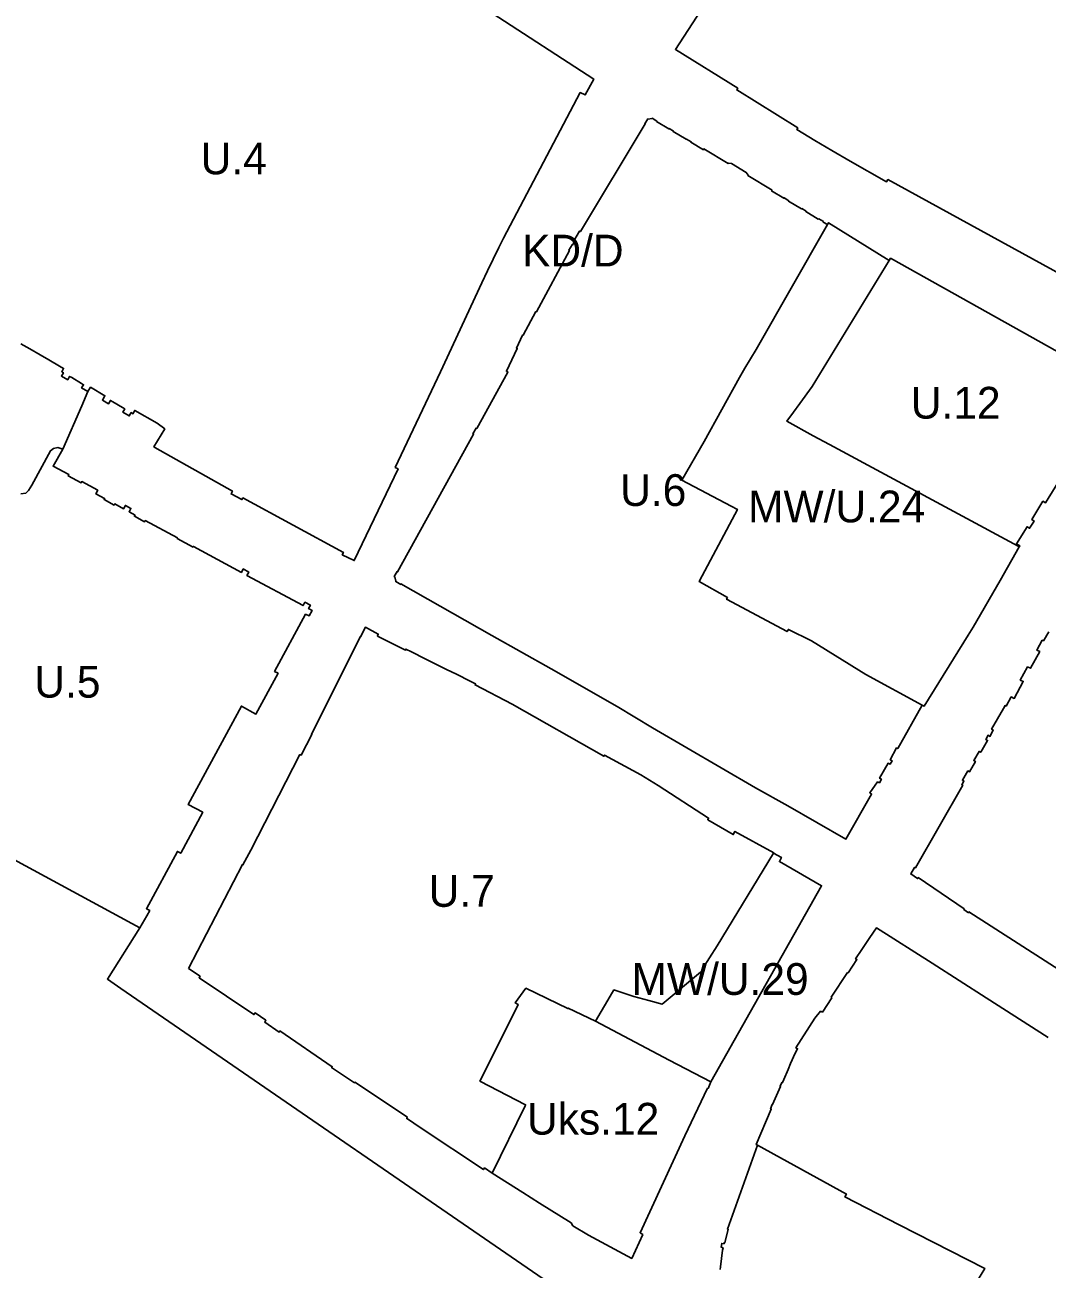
# Model space of a CAD drawing. Extents: x 7423367 to 7424726, y 5546744 to 5548391.
# Drawn here: x 7423601.6 to 7423762.4, y 5547645 to 5547840.8 of the extents above; entities that cross this region are included whole.
import ezdxf

# ---------------------------------------------------------------- set-up
doc = ezdxf.new("R2010")
doc.units = 0
doc.layers.add('linie_rozgraniczajace', color=7, linetype='Continuous')
doc.layers.add('oznaczenia_przeznaczen', color=7, linetype='Continuous')

msp = doc.modelspace()

# ---------------------------------------------------------------- linework, layer by layer
at = {"layer": 'linie_rozgraniczajace'}
for points in [[(7423766.63, 5547800.41), (7423737.4, 5547816.48), (7423737.16, 5547816.11), (7423731.47, 5547819.36), (7423728.55, 5547821.04), (7423725.88, 5547822.62), (7423723.06, 5547824.37), (7423723.22, 5547824.61), (7423713.61, 5547830.6), (7423713.76, 5547830.85), (7423703.96, 5547836.97), (7423711.24, 5547848.23)], [(7423711.24, 5547848.23), (7423703.96, 5547836.97), (7423713.76, 5547830.85), (7423713.61, 5547830.6), (7423723.22, 5547824.61), (7423723.06, 5547824.37), (7423725.88, 5547822.62), (7423728.55, 5547821.04), (7423731.47, 5547819.36), (7423737.16, 5547816.11), (7423737.4, 5547816.48), (7423766.63, 5547800.41)], [(7423675.14, 5547842.66), (7423691.1, 5547832.28), (7423689.77, 5547829.8), (7423688.99, 5547830.18), (7423676.92, 5547807.25), (7423676.17, 5547805.8), (7423674.4, 5547802.11), (7423673.49, 5547800.21), (7423667.01, 5547786.22), (7423659.87, 5547771.16), (7423660.33, 5547770.92), (7423653.43, 5547756.48), (7423651.54, 5547757.4), (7423651.72, 5547757.77), (7423635.91, 5547766.37), (7423635.74, 5547766.1), (7423634.04, 5547766.98), (7423634.25, 5547767.44), (7423622.05, 5547774.29), (7423621.9, 5547774.38), (7423623.61, 5547777.23), (7423622.44, 5547778.13), (7423618.9, 5547780.14), (7423618.6, 5547779.62), (7423618.33, 5547779.78), (7423618.03, 5547779.26), (7423617.02, 5547779.85), (7423617.32, 5547780.37), (7423616.98, 5547780.57), (7423615.42, 5547781.49), (7423615.07, 5547781.7), (7423614.77, 5547781.18), (7423613.79, 5547781.76), (7423614.19, 5547782.45), (7423611.93, 5547783.78), (7423611.52, 5547783.09), (7423610.52, 5547783.68), (7423610.85, 5547784.18), (7423610.5, 5547784.39), (7423608.97, 5547785.29), (7423608.63, 5547785.49), (7423608.34, 5547784.96), (7423607.35, 5547785.55), (7423607.66, 5547786.06), (7423607.4, 5547786.22), (7423607.68, 5547786.74), (7423607.04, 5547787.12), (7423605.39, 5547788.08), (7423604, 5547788.87), (7423602.36, 5547789.82), (7423600.97, 5547790.62)], [(7423690.72, 5547638.24), (7423616.68, 5547689.14), (7423614.59, 5547690.6), (7423619.69, 5547698.66), (7423620.8, 5547700.55), (7423621.24, 5547701.39), (7423620.72, 5547701.68), (7423625.6, 5547710.71), (7423626.13, 5547710.43), (7423629.58, 5547716.88), (7423627.28, 5547718.1), (7423635.66, 5547733.59), (7423637.96, 5547732.34), (7423641.44, 5547738.76), (7423640.9, 5547739.04), (7423645.76, 5547748.04), (7423646.31, 5547747.77), (7423646.78, 5547748.65), (7423646.25, 5547748.93), (7423646.53, 5547749.46), (7423645.66, 5547749.94), (7423645.37, 5547749.41), (7423636.55, 5547754.17), (7423636.83, 5547754.69), (7423635.96, 5547755.17), (7423635.67, 5547754.64), (7423628.12, 5547758.72), (7423628.07, 5547758.63), (7423625.56, 5547759.97), (7423625.6, 5547760.06), (7423620.53, 5547762.78), (7423620.44, 5547762.6), (7423618.84, 5547763.46), (7423618.93, 5547763.62), (7423618, 5547764.19), (7423618.29, 5547764.71), (7423617.42, 5547765.19), (7423617.13, 5547764.66), (7423615.74, 5547765.41), (7423615.65, 5547765.24), (7423614.06, 5547766.1), (7423614.15, 5547766.27), (7423612.77, 5547767), (7423613.07, 5547767.57), (7423610.55, 5547768.93), (7423610.44, 5547768.73), (7423608.43, 5547769.81), (7423608.54, 5547770.02), (7423606.03, 5547771.35), (7423607.56, 5547774.04), (7423610.55, 5547780.86), (7423611.52, 5547783.09), (7423611.93, 5547783.78), (7423614.19, 5547782.45), (7423613.79, 5547781.76), (7423614.77, 5547781.18), (7423615.07, 5547781.7), (7423615.42, 5547781.49), (7423616.98, 5547780.57), (7423617.32, 5547780.37), (7423617.02, 5547779.85), (7423618.03, 5547779.26), (7423618.33, 5547779.78), (7423618.6, 5547779.62), (7423618.9, 5547780.14), (7423622.44, 5547778.13), (7423623.61, 5547777.23), (7423621.9, 5547774.38), (7423622.05, 5547774.29), (7423634.25, 5547767.44), (7423634.04, 5547766.98), (7423635.74, 5547766.1), (7423635.91, 5547766.37), (7423651.72, 5547757.77), (7423651.54, 5547757.4), (7423653.43, 5547756.48), (7423660.33, 5547770.92), (7423659.87, 5547771.16), (7423667.01, 5547786.22), (7423673.49, 5547800.21), (7423674.4, 5547802.11), (7423676.17, 5547805.8), (7423676.92, 5547807.25), (7423688.99, 5547830.18), (7423689.77, 5547829.8), (7423691.1, 5547832.28), (7423675.14, 5547842.66)], [(7423764.13, 5547789.34), (7423737.82, 5547804.09), (7423737.6, 5547803.72), (7423728.07, 5547809.68), (7423727.89, 5547809.38), (7423727.2, 5547809.79), (7423727.24, 5547809.85), (7423726.5, 5547810.29), (7423726.43, 5547810.26), (7423724.49, 5547811.43), (7423724.52, 5547811.48), (7423723.86, 5547811.9), (7423723.78, 5547811.85), (7423721.77, 5547813.05), (7423721.81, 5547813.12), (7423721.07, 5547813.61), (7423721.03, 5547813.53), (7423719.1, 5547814.7), (7423719.16, 5547814.8), (7423715.36, 5547817.09), (7423715.39, 5547817.18), (7423715.11, 5547817.59), (7423712.76, 5547818.99), (7423712.3, 5547819.06), (7423712.24, 5547819), (7423708.43, 5547821.29), (7423708.36, 5547821.17), (7423706.39, 5547822.36), (7423706.43, 5547822.42), (7423705.68, 5547822.86), (7423705.64, 5547822.81), (7423703.62, 5547824.04), (7423703.65, 5547824.1), (7423703, 5547824.49), (7423702.94, 5547824.46), (7423700.98, 5547825.63), (7423701.01, 5547825.67), (7423700.29, 5547826.12), (7423700.23, 5547826.08), (7423699.65, 5547825.99), (7423699.61, 5547826.01), (7423699.13, 5547825.27), (7423699.18, 5547825.23), (7423689.02, 5547808.28), (7423688.87, 5547808.37), (7423687.97, 5547806.84), (7423688.09, 5547806.77), (7423687.76, 5547806.16), (7423687.7, 5547806.2), (7423687.18, 5547805.36), (7423687.27, 5547805.3), (7423682.12, 5547795.64), (7423682, 5547795.7), (7423680.03, 5547791.98), (7423679.92, 5547791.99), (7423678.94, 5547789.95), (7423679.08, 5547789.89), (7423677.37, 5547786.29), (7423677.61, 5547786.17), (7423672.7, 5547777.3), (7423672.6, 5547777.34), (7423672.11, 5547776.45), (7423672.19, 5547776.41), (7423660.24, 5547754.71), (7423660.16, 5547754.75), (7423659.73, 5547753.98), (7423659.79, 5547753.95), (7423659.97, 5547753.24), (7423659.95, 5547753.19), (7423660.73, 5547752.75), (7423660.77, 5547752.82), (7423675.09, 5547744.71), (7423684.39, 5547739.43), (7423694.82, 5547733.51), (7423700.34, 5547730.18), (7423716.57, 5547720.74), (7423721.66, 5547717.88), (7423730.78, 5547712.64), (7423734.83, 5547719.73), (7423734.54, 5547719.94), (7423735.76, 5547721.66), (7423736.05, 5547721.51), (7423736.36, 5547722.07), (7423736.08, 5547722.22), (7423737.43, 5547724.6), (7423737.73, 5547724.43), (7423738.04, 5547724.99), (7423737.75, 5547725.15), (7423738.77, 5547726.99), (7423738.93, 5547726.9), (7423742.81, 5547733.71), (7423743.08, 5547733.55), (7423750.01, 5547744.74), (7423750.79, 5547746), (7423755.07, 5547753.38), (7423758.07, 5547758.65), (7423758.16, 5547758.81), (7423757.62, 5547759.14), (7423759.29, 5547761.83), (7423759.68, 5547761.58), (7423760.4, 5547762.7), (7423760.03, 5547762.97), (7423761.79, 5547765.84), (7423762.21, 5547765.59), (7423765.23, 5547770.52)], [(7423765.23, 5547770.52), (7423762.21, 5547765.59), (7423761.79, 5547765.84), (7423760.03, 5547762.97), (7423760.4, 5547762.7), (7423759.68, 5547761.58), (7423759.29, 5547761.83), (7423757.62, 5547759.14), (7423758.16, 5547758.81), (7423758.07, 5547758.65), (7423757.9, 5547758.76), (7423728.19, 5547774.78), (7423725.65, 5547776.14), (7423721.48, 5547778.45), (7423722.53, 5547779.86), (7423723.56, 5547781.22), (7423725.48, 5547783.89), (7423737.6, 5547803.72), (7423737.82, 5547804.09), (7423764.13, 5547789.34)], [(7423600.97, 5547790.62), (7423602.36, 5547789.82), (7423604, 5547788.87), (7423605.39, 5547788.08), (7423607.04, 5547787.12), (7423607.68, 5547786.74), (7423607.4, 5547786.22), (7423607.66, 5547786.06), (7423607.35, 5547785.55), (7423608.34, 5547784.96), (7423608.63, 5547785.49), (7423608.97, 5547785.29), (7423610.5, 5547784.39), (7423610.85, 5547784.18), (7423610.52, 5547783.68), (7423611.52, 5547783.09), (7423610.55, 5547780.86), (7423607.56, 5547774.04), (7423606.79, 5547774.28), (7423606.12, 5547774.15), (7423605.62, 5547773.78), (7423602.7, 5547768.37), (7423602.15, 5547767.5), (7423601.74, 5547767.1), (7423600.97, 5547766.99)], [(7423600.97, 5547766.99), (7423601.74, 5547767.1), (7423602.15, 5547767.5), (7423602.7, 5547768.37), (7423605.62, 5547773.78), (7423606.12, 5547774.15), (7423606.79, 5547774.28), (7423607.56, 5547774.04), (7423606.03, 5547771.35), (7423608.54, 5547770.02), (7423608.43, 5547769.81), (7423610.44, 5547768.73), (7423610.55, 5547768.93), (7423613.07, 5547767.57), (7423612.77, 5547767), (7423614.15, 5547766.27), (7423614.06, 5547766.1), (7423615.65, 5547765.24), (7423615.74, 5547765.41), (7423617.13, 5547764.66), (7423617.42, 5547765.19), (7423618.29, 5547764.71), (7423618, 5547764.19), (7423618.93, 5547763.62), (7423618.84, 5547763.46), (7423620.44, 5547762.6), (7423620.53, 5547762.78), (7423625.6, 5547760.06), (7423625.56, 5547759.97), (7423628.07, 5547758.63), (7423628.12, 5547758.72), (7423635.67, 5547754.64), (7423635.96, 5547755.17), (7423636.83, 5547754.69), (7423636.55, 5547754.17), (7423645.37, 5547749.41), (7423645.66, 5547749.94), (7423646.53, 5547749.46), (7423646.25, 5547748.93), (7423646.78, 5547748.65), (7423646.31, 5547747.77), (7423645.76, 5547748.04), (7423640.9, 5547739.04), (7423641.44, 5547738.76), (7423637.96, 5547732.34), (7423635.66, 5547733.59), (7423627.28, 5547718.1), (7423629.58, 5547716.88), (7423626.13, 5547710.43), (7423625.6, 5547710.71), (7423620.72, 5547701.68), (7423621.24, 5547701.39), (7423620.8, 5547700.55), (7423619.69, 5547698.66), (7423578.71, 5547720.88)], [(7423770.65, 5547688.01), (7423750.15, 5547701.19), (7423750.06, 5547701.06), (7423749.32, 5547701.58), (7423749.37, 5547701.69), (7423742.18, 5547706.59), (7423742.07, 5547706.44), (7423740.98, 5547707.17), (7423741.59, 5547708.19), (7423741.72, 5547708.12), (7423749.16, 5547721.12), (7423749.02, 5547721.2), (7423749.36, 5547721.79), (7423749.13, 5547721.92), (7423749.97, 5547723.38), (7423750.23, 5547723.22), (7423751.16, 5547724.87), (7423750.91, 5547725.02), (7423751.73, 5547726.46), (7423751.99, 5547726.31), (7423753.08, 5547728.18), (7423752.79, 5547728.35), (7423753.16, 5547728.99), (7423753.45, 5547728.81), (7423753.98, 5547729.8), (7423753.71, 5547729.96), (7423755.59, 5547733.23), (7423755.85, 5547733.68), (7423755.99, 5547733.59), (7423756.8, 5547735.03), (7423757.27, 5547734.79), (7423758.68, 5547737.46), (7423758.21, 5547737.69), (7423759.37, 5547739.76), (7423759.84, 5547739.55), (7423761.29, 5547742.16), (7423760.83, 5547742.39), (7423761.69, 5547743.94), (7423761.85, 5547743.87), (7423762.72, 5547745.26)], [(7423762.72, 5547745.26), (7423761.85, 5547743.87), (7423761.69, 5547743.94), (7423760.83, 5547742.39), (7423761.29, 5547742.16), (7423759.84, 5547739.55), (7423759.37, 5547739.76), (7423758.21, 5547737.69), (7423758.68, 5547737.46), (7423757.27, 5547734.79), (7423756.8, 5547735.03), (7423755.99, 5547733.59), (7423755.85, 5547733.68), (7423755.59, 5547733.23), (7423753.71, 5547729.96), (7423753.98, 5547729.8), (7423753.45, 5547728.81), (7423753.16, 5547728.99), (7423752.79, 5547728.35), (7423753.08, 5547728.18), (7423751.99, 5547726.31), (7423751.73, 5547726.46), (7423750.91, 5547725.02), (7423751.16, 5547724.87), (7423750.23, 5547723.22), (7423749.97, 5547723.38), (7423749.13, 5547721.92), (7423749.36, 5547721.79), (7423749.02, 5547721.2), (7423749.16, 5547721.12), (7423741.72, 5547708.12), (7423741.59, 5547708.19), (7423740.98, 5547707.17), (7423742.07, 5547706.44), (7423742.18, 5547706.59), (7423749.37, 5547701.69), (7423749.32, 5547701.58), (7423750.06, 5547701.06), (7423750.15, 5547701.19), (7423770.65, 5547688.01)], [(7423578.71, 5547720.88), (7423619.69, 5547698.66), (7423614.59, 5547690.6), (7423616.68, 5547689.14), (7423690.72, 5547638.24)], [(7423762.6, 5547681.43), (7423752.86, 5547687.68), (7423744.35, 5547693.13), (7423735.6, 5547698.7), (7423734.56, 5547697.15), (7423733.3, 5547695.29), (7423732.3, 5547693.78), (7423732.52, 5547693.67), (7423731.15, 5547691.6), (7423731.04, 5547691.63), (7423728.49, 5547687.75), (7423728.55, 5547687.66), (7423727.08, 5547685.42), (7423726.81, 5547685.56), (7423725.87, 5547684.47), (7423722.92, 5547679.78), (7423723.17, 5547679.65), (7423722.79, 5547678.94), (7423722.08, 5547677.34), (7423721.68, 5547676.38), (7423721, 5547674.8), (7423720.81, 5547674.33), (7423720.71, 5547674.35), (7423720.43, 5547673.74), (7423720.5, 5547673.68), (7423719.25, 5547670.87), (7423719.16, 5547670.86), (7423718.93, 5547670.16), (7423719.05, 5547670.14), (7423716.69, 5547664.56), (7423716.88, 5547664.46), (7423712.13, 5547651.26), (7423712.28, 5547651.22), (7423711.76, 5547649.1), (7423711.62, 5547649.14), (7423711.61, 5547648.95), (7423711.25, 5547648.99), (7423711.16, 5547648.39), (7423711.46, 5547648.32), (7423711.39, 5547647.91), (7423711.07, 5547645.3), (7423711.02, 5547644.88)], [(7423749.78, 5547640.35), (7423752.65, 5547645.04), (7423739.17, 5547651.95), (7423730.63, 5547656.33), (7423730.86, 5547656.77), (7423716.88, 5547664.46), (7423716.69, 5547664.56), (7423719.05, 5547670.14), (7423718.93, 5547670.16), (7423719.16, 5547670.86), (7423719.25, 5547670.87), (7423720.5, 5547673.68), (7423720.43, 5547673.74), (7423720.71, 5547674.35), (7423720.81, 5547674.33), (7423721, 5547674.8), (7423721.68, 5547676.38), (7423722.08, 5547677.34), (7423722.79, 5547678.94), (7423723.17, 5547679.65), (7423722.92, 5547679.78), (7423725.87, 5547684.47), (7423726.81, 5547685.56), (7423727.08, 5547685.42), (7423728.55, 5547687.66), (7423728.49, 5547687.75), (7423731.04, 5547691.63), (7423731.15, 5547691.6), (7423732.52, 5547693.67), (7423732.3, 5547693.78), (7423733.3, 5547695.29), (7423734.56, 5547697.15), (7423735.6, 5547698.7), (7423744.35, 5547693.13), (7423752.86, 5547687.68), (7423762.6, 5547681.43)], [(7423711.02, 5547644.88), (7423711.07, 5547645.3), (7423711.39, 5547647.91), (7423711.46, 5547648.32), (7423711.16, 5547648.39), (7423711.25, 5547648.99), (7423711.61, 5547648.95), (7423711.62, 5547649.14), (7423711.76, 5547649.1), (7423712.28, 5547651.22), (7423712.13, 5547651.26), (7423716.88, 5547664.46), (7423730.86, 5547656.77), (7423730.63, 5547656.33), (7423739.17, 5547651.95), (7423752.65, 5547645.04), (7423749.78, 5547640.35)]]:
    msp.add_lwpolyline(points, dxfattribs=at)
for points in [[(7423659.73, 5547753.98), (7423660.16, 5547754.75), (7423660.24, 5547754.71), (7423672.19, 5547776.41), (7423672.11, 5547776.45), (7423672.6, 5547777.34), (7423672.7, 5547777.3), (7423677.61, 5547786.17), (7423677.37, 5547786.29), (7423679.08, 5547789.89), (7423678.94, 5547789.95), (7423679.92, 5547791.99), (7423680.03, 5547791.98), (7423682, 5547795.7), (7423682.12, 5547795.64), (7423687.27, 5547805.3), (7423687.18, 5547805.36), (7423687.7, 5547806.2), (7423687.76, 5547806.16), (7423688.09, 5547806.77), (7423687.97, 5547806.84), (7423688.87, 5547808.37), (7423689.02, 5547808.28), (7423699.18, 5547825.23), (7423699.13, 5547825.27), (7423699.61, 5547826.01), (7423699.65, 5547825.99), (7423700.23, 5547826.08), (7423700.29, 5547826.12), (7423701.01, 5547825.67), (7423700.98, 5547825.63), (7423702.94, 5547824.46), (7423703, 5547824.49), (7423703.65, 5547824.1), (7423703.62, 5547824.04), (7423705.64, 5547822.81), (7423705.68, 5547822.86), (7423706.43, 5547822.42), (7423706.39, 5547822.36), (7423708.36, 5547821.17), (7423708.43, 5547821.29), (7423712.24, 5547819), (7423712.3, 5547819.06), (7423712.76, 5547818.99), (7423715.11, 5547817.59), (7423715.39, 5547817.18), (7423715.36, 5547817.09), (7423719.16, 5547814.8), (7423719.1, 5547814.7), (7423721.03, 5547813.53), (7423721.07, 5547813.61), (7423721.81, 5547813.12), (7423721.77, 5547813.05), (7423723.78, 5547811.85), (7423723.86, 5547811.9), (7423724.52, 5547811.48), (7423724.49, 5547811.43), (7423726.43, 5547810.26), (7423726.5, 5547810.29), (7423727.24, 5547809.85), (7423727.2, 5547809.79), (7423727.89, 5547809.38), (7423716.65, 5547789.74), (7423714.87, 5547786.8), (7423714.03, 5547785.32), (7423708.47, 5547775.24), (7423704.98, 5547769.14), (7423712.73, 5547765.08), (7423713.72, 5547764.56), (7423707.75, 5547753.3), (7423707.7, 5547753.2), (7423712.15, 5547750.67), (7423712.01, 5547750.4), (7423721.52, 5547745.31), (7423721.75, 5547745.65), (7423725.35, 5547743.84), (7423733.94, 5547738.57), (7423742.81, 5547733.71), (7423738.93, 5547726.9), (7423738.77, 5547726.99), (7423737.75, 5547725.15), (7423738.04, 5547724.99), (7423737.73, 5547724.43), (7423737.43, 5547724.6), (7423736.08, 5547722.22), (7423736.36, 5547722.07), (7423736.05, 5547721.51), (7423735.76, 5547721.66), (7423734.54, 5547719.94), (7423734.83, 5547719.73), (7423730.78, 5547712.64), (7423721.66, 5547717.88), (7423716.57, 5547720.74), (7423700.34, 5547730.18), (7423694.82, 5547733.51), (7423684.39, 5547739.43), (7423675.09, 5547744.71), (7423660.77, 5547752.82), (7423660.73, 5547752.75), (7423659.95, 5547753.19), (7423659.97, 5547753.24), (7423659.79, 5547753.95)], [(7423704.98, 5547769.14), (7423708.47, 5547775.24), (7423714.03, 5547785.32), (7423714.87, 5547786.8), (7423716.65, 5547789.74), (7423727.89, 5547809.38), (7423728.07, 5547809.68), (7423737.6, 5547803.72), (7423725.48, 5547783.89), (7423723.56, 5547781.22), (7423722.53, 5547779.86), (7423721.48, 5547778.45), (7423725.65, 5547776.14), (7423728.19, 5547774.78), (7423757.9, 5547758.76), (7423758.07, 5547758.65), (7423755.07, 5547753.38), (7423750.79, 5547746), (7423750.01, 5547744.74), (7423743.08, 5547733.55), (7423742.81, 5547733.71), (7423733.94, 5547738.57), (7423725.35, 5547743.84), (7423721.75, 5547745.65), (7423721.52, 5547745.31), (7423712.01, 5547750.4), (7423712.15, 5547750.67), (7423707.7, 5547753.2), (7423707.75, 5547753.3), (7423713.72, 5547764.56), (7423712.73, 5547765.08)], [(7423627.36, 5547692.29), (7423635.82, 5547708.63), (7423635.92, 5547708.58), (7423637.13, 5547710.93), (7423644.87, 5547725.95), (7423645.06, 5547725.86), (7423646.76, 5547729.09), (7423646.69, 5547729.13), (7423654.35, 5547744.5), (7423654.42, 5547744.48), (7423655.19, 5547746), (7423657.21, 5547744.93), (7423657.06, 5547744.62), (7423661.47, 5547742.38), (7423661.55, 5547742.55), (7423662.41, 5547742.12), (7423664.6, 5547741.03), (7423665.76, 5547740.46), (7423667.96, 5547739.36), (7423669.49, 5547738.62), (7423671.69, 5547737.5), (7423672.53, 5547737.09), (7423672.45, 5547736.92), (7423678.26, 5547733.87), (7423692.72, 5547725.7), (7423692.82, 5547725.87), (7423698.54, 5547722.74), (7423701.25, 5547721.08), (7423709.19, 5547715.95), (7423709.05, 5547715.69), (7423713.07, 5547713.37), (7423713.33, 5547713.87), (7423719.44, 5547710.49), (7423719.41, 5547710.41), (7423710.54, 5547695.82), (7423708.14, 5547692.09), (7423708.22, 5547692.02), (7423707.92, 5547691.69), (7423701.87, 5547686.67), (7423699.78, 5547687.24), (7423697.41, 5547687.89), (7423694.28, 5547688.91), (7423693.67, 5547687.94), (7423691.41, 5547683.97), (7423687.1, 5547686.05), (7423687.05, 5547685.96), (7423680.43, 5547689.17), (7423678.77, 5547686.85), (7423679.21, 5547686.62), (7423678.88, 5547685.92), (7423673.21, 5547674.56), (7423680.39, 5547670.82), (7423680.31, 5547670.67), (7423675.15, 5547660.07), (7423673.93, 5547660.88), (7423673.76, 5547660.62), (7423663.96, 5547667.16), (7423661.67, 5547668.7), (7423661.78, 5547668.86), (7423653.53, 5547674.39), (7423653.44, 5547674.26), (7423649.87, 5547676.68), (7423649.96, 5547676.81), (7423641.74, 5547682.44), (7423641.62, 5547682.26), (7423639.34, 5547683.82), (7423639.53, 5547684.13), (7423637.82, 5547685.29), (7423637.64, 5547685.02), (7423629.01, 5547690.81), (7423629.18, 5547691.07)], [(7423627.36, 5547692.29), (7423629.18, 5547691.07), (7423629.01, 5547690.81), (7423637.64, 5547685.02), (7423637.82, 5547685.29), (7423639.53, 5547684.13), (7423639.34, 5547683.82), (7423641.62, 5547682.26), (7423641.74, 5547682.44), (7423649.96, 5547676.81), (7423649.87, 5547676.68), (7423653.44, 5547674.26), (7423653.53, 5547674.39), (7423661.78, 5547668.86), (7423661.67, 5547668.7), (7423663.96, 5547667.16), (7423673.76, 5547660.62), (7423673.93, 5547660.88), (7423675.15, 5547660.07), (7423679.95, 5547657.03), (7423682.55, 5547655.31), (7423687.55, 5547652.24), (7423687.8, 5547651.79), (7423690.26, 5547650.32), (7423697.08, 5547646.65), (7423698.83, 5547650.38), (7423698.39, 5547650.69), (7423705.44, 5547665.93), (7423709.01, 5547673.42), (7423709.11, 5547673.41), (7423709.54, 5547674.41), (7423726.96, 5547705.31), (7423720.33, 5547709.12), (7423720.64, 5547709.76), (7423719.41, 5547710.41), (7423719.44, 5547710.49), (7423713.33, 5547713.87), (7423713.07, 5547713.37), (7423709.05, 5547715.69), (7423709.19, 5547715.95), (7423701.25, 5547721.08), (7423698.54, 5547722.74), (7423692.82, 5547725.87), (7423692.72, 5547725.7), (7423678.26, 5547733.87), (7423672.45, 5547736.92), (7423672.53, 5547737.09), (7423671.69, 5547737.5), (7423669.49, 5547738.62), (7423667.96, 5547739.36), (7423665.76, 5547740.46), (7423664.6, 5547741.03), (7423662.41, 5547742.12), (7423661.55, 5547742.55), (7423661.47, 5547742.38), (7423657.06, 5547744.62), (7423657.21, 5547744.93), (7423655.19, 5547746), (7423654.42, 5547744.48), (7423654.35, 5547744.5), (7423646.69, 5547729.13), (7423646.76, 5547729.09), (7423645.06, 5547725.86), (7423644.87, 5547725.95), (7423637.13, 5547710.93), (7423635.92, 5547708.58), (7423635.82, 5547708.63)], [(7423691.41, 5547683.97), (7423693.67, 5547687.94), (7423694.28, 5547688.91), (7423697.41, 5547687.89), (7423699.78, 5547687.24), (7423701.87, 5547686.67), (7423707.92, 5547691.69), (7423708.22, 5547692.02), (7423708.14, 5547692.09), (7423710.54, 5547695.82), (7423719.41, 5547710.41), (7423720.64, 5547709.76), (7423720.33, 5547709.12), (7423726.96, 5547705.31), (7423709.54, 5547674.41), (7423702.98, 5547677.87)], [(7423673.21, 5547674.56), (7423678.88, 5547685.92), (7423679.21, 5547686.62), (7423678.77, 5547686.85), (7423680.43, 5547689.17), (7423687.05, 5547685.96), (7423687.1, 5547686.05), (7423691.41, 5547683.97), (7423702.98, 5547677.87), (7423709.54, 5547674.41), (7423709.11, 5547673.41), (7423709.01, 5547673.42), (7423705.44, 5547665.93), (7423698.39, 5547650.69), (7423698.83, 5547650.38), (7423697.08, 5547646.65), (7423690.26, 5547650.32), (7423687.8, 5547651.79), (7423687.55, 5547652.24), (7423682.55, 5547655.31), (7423679.95, 5547657.03), (7423675.15, 5547660.07), (7423680.31, 5547670.67), (7423680.39, 5547670.82)]]:
    msp.add_lwpolyline(points, close=True, dxfattribs=at)

# ---------------------------------------------------------------- texts
at = {"layer": 'oznaczenia_przeznaczen'}
for s, p in [('U.4', (7423629.26, 5547817.3)), ('KD/D', (7423679.83, 5547802.79)), ('U.12', (7423741, 5547778.84)), ('U.6', (7423695.27, 5547765.09)), ('MW/U.24', (7423715.4, 5547762.51)), ('U.5', (7423603.09, 5547734.92)), ('U.7', (7423665.13, 5547701.99)), ('MW/U.29', (7423697.06, 5547688.12)), ('Uks.12', (7423680.61, 5547666.12))]:
    msp.add_text(s, height=5, dxfattribs=at).set_placement(p)

doc.saveas('drawing.dxf')
